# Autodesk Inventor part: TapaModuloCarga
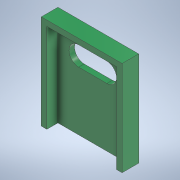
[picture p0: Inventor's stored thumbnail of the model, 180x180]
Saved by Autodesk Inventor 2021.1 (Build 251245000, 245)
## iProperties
Created: 2021-06
Part Number: TapaModuloCarga
Material: Genérico
Document SubType Name: Modeling
Designer: Ricardo
Density: 1 g/cm^3
Appearance: Valor por defecto
Author: Ricardo
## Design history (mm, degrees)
sketch "Boceto1"
  geometry: L1 (-14.6, -16.1)-(14.6, -16.1); L2 (12.6, -16.1)-(12.6, 16.1); L3 (12.6, 16.1)-(-12.6, 16.1); L4 (-12.6, 16.1)-(-12.6, -16.1); L5 (-12.6, -16.1)-(12.6, 16.1); L6 (12.6, -16.1)-(-12.6, 16.1); L7 (14.6, 18.1)-(14.6, -16.1); L8 (-14.6, -16.1)-(-14.6, 18.1); L9 (-14.6, 18.1)-(14.6, 18.1); L10 (-8.6, 8.6)-(8.6, 8.6); L11 (-5.1, 5.1)-(5.1, 5.1); L12 (5.1, 12.1)-(-5.1, 12.1); A1 r 3.5 centre (-5.1, 8.6) between (-5.1, 12.1) and (-5.1, 5.1); A2 r 3.5 centre (5.1, 8.6) between (5.1, 5.1) and (5.1, 12.1); 2 further points
  constraints: 26 end point, 6 point on circle, 4 parallel, 4 tangent, 3 midpoint, 3 point on line, 2 centre point, 2 perpendicular, 1 horizontal
  dimensions: "d7" = 25.2 distance between parallel lines of L2 L4; "d8" = 2 distance between parallel lines of L7 L2; "d9" = 2 distance between parallel lines of L8 L4; "d10" = 2 distance between parallel lines of L3 L9; "d11" = 32.2 distance between parallel lines of L1 L3; "d12" = 4 distance between parallel lines of L12 L3; "d13" = 7 distance between parallel lines of L12 L11; "d15" = 7.5 distance from line of L2 A2.centre; "d16" = 7.5 distance from line of L4 A1.centre
extrude "Extrusión1" new body sketch "Boceto1" distance "d3" = 2; taper "d4" = 0 deg
extrude "Extrusión2" join sketch "Boceto1" distance "d5" = 4; taper "d6" = 0 deg
node "Sólido1"
